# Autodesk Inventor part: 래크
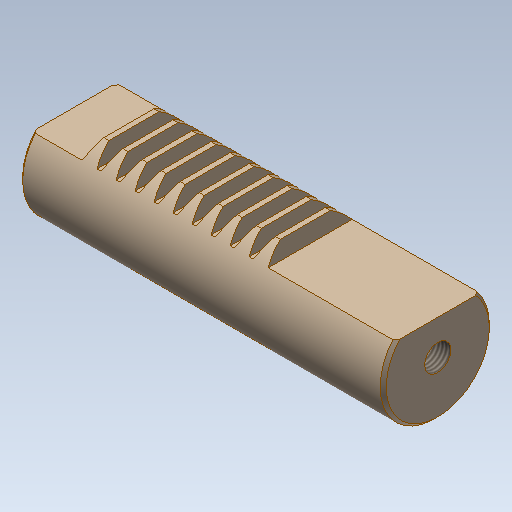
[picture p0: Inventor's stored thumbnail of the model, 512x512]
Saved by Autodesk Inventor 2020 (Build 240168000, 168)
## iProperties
Created: 2019-06
Part Number: 래크
Material: 스테인리스강
Document SubType Name: Modeling
Designer: mduedu
Density: 1 g/cm^3
Appearance: 기본값(1)
Author: mduedu
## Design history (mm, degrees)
sketch "스케치1"
  geometry: L1 (0, 0)-(120, 0); L2 (120, 0)-(120, 34); L3 (120, 34)-(0, 34); L4 (0, 34)-(0, 0)
  constraints: 8 end point, 2 parallel, 1 horizontal, 1 perpendicular
  dimensions: "d0" = 120 distance of L1.start L1.end; "d1" = 34 distance of L1.end L2.end
extrude "돌출1" new body sketch "스케치1" stored distance "d2" = 36; taper "d3" = 0 deg
sketch "스케치2"
  geometry: L1 (0, 0)-(120, 0) reference; L2 (120, 0)-(120, 34) reference; L3 (120, 34)-(0, 34) reference; L4 (0, 34)-(0, 0) reference; L5 (15.1, 29.5)-(16.42, 29.5); L6 (18.058, 34)-(13.462, 34); L7 (15.76, 34)-(15.76, 29.5); L8 (13.462, 34)-(15.1, 29.5); L9 (18.058, 34)-(16.42, 29.5); L10 (14.19, 32)-(17.33, 32); 1 further point
  constraints: 12 end point, 2 midpoint, 2 point on line, 1 collinear, 1 horizontal, 1 parallel, 1 perpendicular, 1 symmetric about line
  dimensions: "d4" = 20 deg angle of L9 L7; "d5" = 2 distance between parallel lines of L10 L6; "d7" = 4.5 distance between parallel lines of L5 L6 (= 2.25 x d5); "d8" = 3.14 distance of L10.start L10.end; "d9" = 15.76 distance between parallel lines of L4 L7
extrude "돌출2" cut sketch "스케치2" extent not by distance; stored distance "d10" = 36; taper "d11" = 0 deg
sketch "스케치3"
  geometry: L1 (120, 34)-(80.858, 34) reference; L2 (68.298, 34)-(66.66, 29.5) reference; L3 (66.66, 29.5)-(65.34, 29.5) reference; L4 (65.34, 29.5)-(63.702, 34) reference; L5 (62.018, 34)-(60.38, 29.5) reference; L6 (60.38, 29.5)-(59.06, 29.5) reference; L7 (59.06, 29.5)-(57.422, 34) reference; L8 (57.422, 34)-(55.738, 34) reference; L9 (55.738, 34)-(54.1, 29.5) reference; L10 (54.1, 29.5)-(52.78, 29.5) reference; L11 (52.78, 29.5)-(51.142, 34) reference; L12 (51.142, 34)-(49.458, 34) reference; L13 (49.458, 34)-(47.82, 29.5) reference; L14 (47.82, 29.5)-(46.5, 29.5) reference; L15 (46.5, 29.5)-(44.862, 34) reference; L16 (44.862, 34)-(43.178, 34) reference; L17 (43.178, 34)-(41.54, 29.5) reference; L18 (41.54, 29.5)-(40.22, 29.5) reference; L19 (40.22, 29.5)-(38.582, 34) reference; L20 (38.582, 34)-(36.898, 34) reference; L21 (36.898, 34)-(35.26, 29.5) reference; L22 (35.26, 29.5)-(33.94, 29.5) reference; L23 (33.94, 29.5)-(32.302, 34) reference; L24 (32.302, 34)-(30.618, 34) reference; L25 (30.618, 34)-(28.98, 29.5) reference; L26 (28.98, 29.5)-(27.66, 29.5) reference; L27 (27.66, 29.5)-(26.022, 34) reference; L28 (26.022, 34)-(24.338, 34) reference; L29 (24.338, 34)-(22.7, 29.5) reference; L30 (22.7, 29.5)-(21.38, 29.5) reference; L31 (21.38, 29.5)-(19.742, 34) reference; L32 (19.742, 34)-(18.058, 34) reference; L33 (18.058, 34)-(16.42, 29.5) reference; L34 (16.42, 29.5)-(15.1, 29.5) reference; L35 (15.1, 29.5)-(13.462, 34) reference; L36 (0, 34)-(0, 0) reference; L37 (0, 0)-(120, 0) reference; L38 (120, 0)-(120, 34) reference; L39 (13.462, 34)-(0, 34) reference; L40 (80.858, 34)-(79.22, 29.5) reference; L41 (79.22, 29.5)-(77.9, 29.5) reference; L42 (77.9, 29.5)-(76.262, 34) reference; L43 (74.578, 34)-(72.94, 29.5) reference; L44 (72.94, 29.5)-(71.62, 29.5) reference; L45 (71.62, 29.5)-(69.982, 34) reference; L46 (69.982, 34)-(68.298, 34) reference; L47 (63.702, 34)-(62.018, 34) reference; L48 (76.262, 34)-(74.578, 34) reference; L49 (15.1, 29.5)-(0, 29.5); L50 (79.22, 29.5)-(120, 29.5); 1 further point
  constraints: 4 end point, 2 perpendicular, 2 point on line
extrude "돌출3" cut sketch "스케치3" extent not by distance; stored distance "d18" = 36; taper "d19" = 0 deg
sketch "스케치4"
  geometry: L1 (0, 29.5)-(0, 0) reference; L2 (0, 0)-(120, 0) reference; L3 (120, 0)-(120, 29.5) reference; L4 (76.262, 34)-(74.578, 34) reference; L5 (68.298, 34)-(66.66, 29.5) reference; L6 (66.66, 29.5)-(65.34, 29.5) reference; L7 (65.34, 29.5)-(63.702, 34) reference; L8 (62.018, 34)-(60.38, 29.5) reference; L9 (60.38, 29.5)-(59.06, 29.5) reference; L10 (59.06, 29.5)-(57.422, 34) reference; L11 (57.422, 34)-(55.738, 34) reference; L12 (55.738, 34)-(54.1, 29.5) reference; L13 (54.1, 29.5)-(52.78, 29.5) reference; L14 (52.78, 29.5)-(51.142, 34) reference; L15 (51.142, 34)-(49.458, 34) reference; L16 (49.458, 34)-(47.82, 29.5) reference; L17 (47.82, 29.5)-(46.5, 29.5) reference; L18 (46.5, 29.5)-(44.862, 34) reference; L19 (44.862, 34)-(43.178, 34) reference; L20 (43.178, 34)-(41.54, 29.5) reference; L21 (41.54, 29.5)-(40.22, 29.5) reference; L22 (40.22, 29.5)-(38.582, 34) reference; L23 (38.582, 34)-(36.898, 34) reference; L24 (36.898, 34)-(35.26, 29.5) reference; L25 (35.26, 29.5)-(33.94, 29.5) reference; L26 (33.94, 29.5)-(32.302, 34) reference; L27 (32.302, 34)-(30.618, 34) reference; L28 (30.618, 34)-(28.98, 29.5) reference; L29 (28.98, 29.5)-(27.66, 29.5) reference; L30 (27.66, 29.5)-(26.022, 34) reference; L31 (26.022, 34)-(24.338, 34) reference; L32 (24.338, 34)-(22.7, 29.5) reference; L33 (22.7, 29.5)-(21.38, 29.5) reference; L34 (21.38, 29.5)-(19.742, 34) reference; L35 (19.742, 34)-(18.058, 34) reference; L36 (18.058, 34)-(16.42, 29.5) reference; L37 (16.42, 29.5)-(0, 29.5) reference; L38 (30, 0)-(76, 0); L39 (76, 0)-(76, 4); L40 (76, 4)-(30, 4); L41 (30, 4)-(30, 0); L42 (120, 29.5)-(77.9, 29.5) reference; L43 (77.9, 29.5)-(76.262, 34) reference; L44 (74.578, 34)-(72.94, 29.5) reference; L45 (72.94, 29.5)-(71.62, 29.5) reference; L46 (71.62, 29.5)-(69.982, 34) reference; L47 (69.982, 34)-(68.298, 34) reference; L48 (63.702, 34)-(62.018, 34) reference; 1 further point
  constraints: 8 end point, 2 parallel, 1 horizontal, 1 perpendicular, 1 point on line
  dimensions: "d20" = 30 distance between parallel lines of L41 L1; "d22" = 46 distance between parallel lines of L39 L41; "d23" = 4 distance between parallel lines of L2 L40
extrude "돌출4" cut sketch "스케치4" extent not by distance; stored distance "d24" = 36; taper "d25" = 0 deg
sketch "스케치5"
  geometry: L1 (36, 0)-(0, 0) reference; C1 r 18 at (18, 18); 2 further points
  constraints: 1 centre point, 1 midpoint, 1 tangent, 1 vertical alignment
  dimensions: "d26" = 36 diameter of C1
extrude "돌출5" sketch "스케치5" extent not by distance; stored distance "d27" = 36; taper "d28" = 0 deg
chamfer "모따기1" distance "d29" = 1; stored, may be unused: second distance "d30" = 2, angle "d31" = 45 deg
hole "구멍1" diameter "d34" = 8.647; stored, may be unused: countersink angle "d38" = 90 deg, drill point angle "d40" = 118 deg; dims "d32" = 10, "d33" = 10, "d35" = 20, "d36" = 4, "d37" = 2, "d39" = 22
node "솔리드1"
pattern_linear "직사각형 패턴1" dims "d14" = 6.28, "d17" = 6.28
node "투영된 루프1"
node "투영된 루프2"
node "투영된 루프3"
